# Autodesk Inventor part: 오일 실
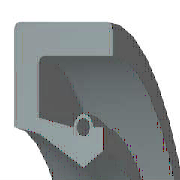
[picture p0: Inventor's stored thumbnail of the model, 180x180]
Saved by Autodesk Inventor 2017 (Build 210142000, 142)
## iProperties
IsCustomPart: 1
Created: 2015-12
Part Number: 오일 실
Material: 고무
Description: 오일-실
Document SubType Name: Modeling
Standard: KS B 2804
Designer: mdu
Standards Organization: KS
Language: ko-KR
Size Designation: S - 15 30 7
Categories: <MemberInstance><Categories><Category DisplayName="샤프트 부품" InternalName="7f7aeb1f-a693-4053-b835-cee3144e0d98" Mnemonic="SHFT"><Category DisplayName="실링" Intern
Density: 0.93 g/cm^3
Appearance: 고무 - 검은색 - 버전 1.1
Mass: 1.64364 g
Surface Area: 26.6454 cm^2
Volume: 1.76736 cm^3
Author: mdu
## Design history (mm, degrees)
revolve "본체" stored, may be unused: angle "d17" = 90 deg
revolve "스프링1" stored, may be unused: angle "d18" = 90 deg
body "Solid1"
sketch "스케치1"
  geometry: L1 (0, 15)-(7, 15); L2 (7, 15)-(7, 13.75); L3 (7, 13.75)-(1.75, 13.75); L4 (0, 15)-(0, 9.6); L5 (0, 9.6)-(1.75, 9.25); L6 (1.75, 9.25)-(4.9, 7.5); L7 (4.9, 7.5)-(0, 7.5); L8 (6.3, 8.375)-(6.3, 9.6); L9 (0, 0)-(9.586, 0) reference; L10 (4.9, 7.5)-(6.3, 8.375); L11 (0, 18)-(0, -3) reference; L12 (-1.917, 0)-(11.503, 0) reference; L13 (4.2, 9.6)-(1.75, 10.09); L14 (1.75, 10.09)-(1.75, 13.75); L15 (6.3, 9.6)-(5.6, 9.6); C1 r 0.455 at (4.9, 9.6); A1 r 0.7 centre (4.9, 9.6) between (5.6, 9.6) and (4.2, 9.6)
  constraints: 26 end point, 5 horizontal alignment, 4 perpendicular, 2 centre point, 2 collinear, 2 horizontal, 2 parallel, 2 point on circle, 2 point on line, 2 vertical alignment, 1 coincident
  dimensions: "d0" = 30 diameter of L1 L9 (= SD2); "d1" = 16.75 diameter of L8.start L9 (= ABDM); "d2" = 1.25 distance of L1.end L2.end (computed from SD); "d3" = 0.91 diameter of C1 (= SPDI); "d4" = 1.4 diameter of A1 (= SPDA); "d5" = 15 diameter of L6.end L9 (= NND); "d6" = 18.5 diameter of L5.end L9 (= TKDM); "d7" = 19.2 diameter of L4.end L9 (= HLDM); "d8" = 4.9 distance from line of C1.centre L4 (= SPDST); "d9" = 6.3 distance between parallel lines of L8 L4 (= SDI); "d10" = 7 distance between parallel lines of L2 L4 (= SWDT); "d12" = 1.75 distance between parallel lines of L14 L4 (= SD)
fillet "모깎기1" dims "d11" = 0.3 (= RR)
other parameters: "SD2" = 30 [user parameter; used in 1 equation term], "SWDT" = 7 [user parameter; used in 1 equation term], "RR" = 0.3 [user parameter; used in 1 equation term], "SD" = 1.75 [user parameter; used in 2 equation terms], "NND" = 15 [user parameter; used in 1 equation term], "SPDA" = 1.4 [user parameter; used in 1 equation term], "SPDI" = 0.91 [user parameter; used in 1 equation term], "TKDM" = 18.5 [user parameter; used in 1 equation term], "HLDM" = 19.2 [user parameter; used in 1 equation term], "ABDM" = 16.75 [user parameter; used in 1 equation term], "SDI" = 6.3 [user parameter; used in 1 equation term], "SPDST" = 4.9 [user parameter; used in 1 equation term], "d13" = 0, "d14" = 0, "d15" = 0, "LAB" = 0.35 [user parameter]
